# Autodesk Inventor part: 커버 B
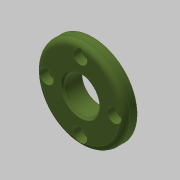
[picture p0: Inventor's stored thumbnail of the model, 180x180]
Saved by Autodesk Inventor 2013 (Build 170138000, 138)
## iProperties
Created: 2019-01
Part Number: 커버 B
Material: 알루미늄 6061
Document SubType Name: Modeling
Designer: mduedu
Density: 1 g/cm^3
Author: mduedu
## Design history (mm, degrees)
sketch "스케치1"
  geometry: L1 (0, 0)-(7, 0); L2 (7, 0)-(7, 25); L3 (7, 25)-(0, 25); L4 (0, 25)-(0, 0); L5 (7, 0)-(11, 0); L6 (11, 0)-(11, 14); L7 (11, 14)-(7, 14); L8 (7, 14)-(7, 0)
  constraints: 16 end point, 4 parallel, 2 horizontal, 2 perpendicular
  dimensions: "d0" = 50 diameter of L3 L1; "d2" = 11 distance between parallel lines of L6 L4; "d3" = 7 distance of L2.end L3.end; "d4" = 28 diameter of L7 L5
revolve "회전1" sketch "스케치1" stored, may be unused: angle "d5" = 90 deg
sketch "스케치2"
  geometry: C1 r 10 at (0, 0); 1 further point
  constraints: 1 centre point, 1 coincident
  dimensions: "d6" = 20 diameter of C1
extrude "돌출1" cut sketch "스케치2" stored distance "d7" = 10; taper "d8" = 0 deg
chamfer "모따기1" distance "d9" = 1; stored, may be unused: second distance "d10" = 2, angle "d11" = 45 deg
fillet "모깎기1" dims "d12" = 3
sketch "스케치3" dims "d13" = 38
  geometry: 6 further points
  constraints: 2 vertical alignment, 1 coincident, 7 other
  dimensions: "d16" = 360 deg dimension on point (0, 0) point (0, 19) (derived)
chamfer "모따기2" distance "d18" = 1; stored, may be unused: second distance "d19" = 2, angle "d20" = 45 deg
sketch "스케치4"
  geometry: 4 further points
  constraints: 4 other
hole "구멍1" sketch "스케치4" at (-19, 0), (0, -19), (19, 0), (0, 19) diameter "d21" = 4.5; stored, may be unused: countersink angle "d25" = 90 deg, drill point angle "d27" = 0 deg; dims "d22" = 6, "d23" = 8, "d24" = 4.6, "d26" = 8
node "솔리드1"
